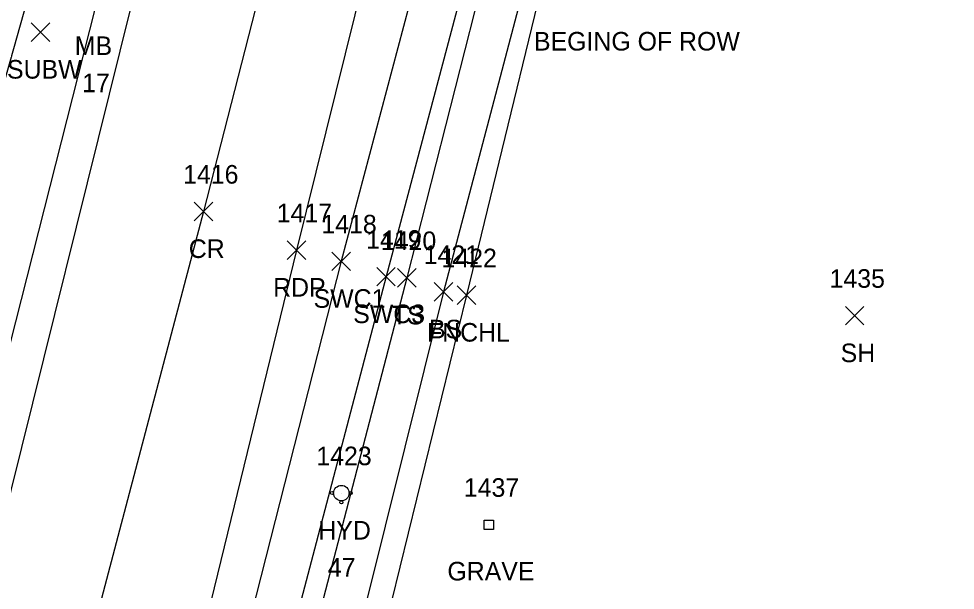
# Model space of a CAD drawing. Extents: x 1477930 to 1480780, y 774090 to 784647.
# Drawn here: x 1479293.7 to 1479394.4, y 774209.8 to 774271.3 of the extents above; entities that cross this region are included whole.
import ezdxf

# ---------------------------------------------------------------- set-up
doc = ezdxf.new("R2010")
doc.units = 0
for name, color, linetype in [('L_A', 7, 'Continuous'), ('L_C', 7, 'Continuous'), ('L_I', 7, 'Continuous'), ('L_TIC', 7, 'Continuous'), ('LCEM', 7, 'Continuous'), ('LELB', 7, 'Continuous'), ('LFNC', 7, 'Continuous'), ('P_A', 7, 'Continuous'), ('P_I', 7, 'Continuous'), ('P_TIC', 7, 'Continuous'), ('PET', 7, 'Continuous'), ('PRC', 7, 'Continuous'), ('R_A', 7, 'Continuous'), ('R_I', 7, 'Continuous'), ('R_TIC', 7, 'Continuous'), ('RSW', 7, 'Continuous'), ('U_A', 7, 'Continuous'), ('U_C', 7, 'Continuous'), ('U_I', 7, 'Continuous'), ('U_TIC', 7, 'Continuous'), ('UWFH', 7, 'Continuous')]:
    doc.layers.add(name, color=color, linetype=linetype)

msp = doc.modelspace()

# ---------------------------------------------------------------- linework, layer by layer
at = {"layer": 'L_TIC'}
for points in [[(1479334.38, 774242.42), (1479336.38, 774244.42)], [(1479336.38, 774242.42), (1479334.38, 774244.42)], [(1479338.33, 774240.92), (1479340.33, 774242.92)], [(1479340.33, 774240.92), (1479338.33, 774242.92)], [(1479340.81, 774240.57), (1479342.81, 774242.57)], [(1479342.81, 774240.57), (1479340.81, 774242.57)], [(1479382.55, 774238.36), (1479384.55, 774240.36)], [(1479384.55, 774238.36), (1479382.55, 774240.36)]]:
    msp.add_lwpolyline(points, dxfattribs=at)
at = {"layer": 'LCEM'}
for p, q in [((1479343.71, 774216.37), (1479343.71, 774217.37)), ((1479343.71, 774217.37), (1479344.71, 774217.37)), ((1479344.21, 774216.87), (1479344.21, 774216.87)), ((1479344.21, 774216.87), (1479344.21, 774216.87)), ((1479344.71, 774217.37), (1479344.71, 774216.37)), ((1479344.71, 774216.37), (1479343.71, 774216.37))]:
    msp.add_line(p, q, dxfattribs=at)
at = {"layer": 'LELB'}
for points in [[(1479286.59, 774212.27), (1479303.75, 774279.72), (1479306.97, 774294.46), (1479314.06, 774320.63), (1479317.48, 774329.95), (1479319.72, 774342.37), (1479300.83, 774349.59), (1479294.56, 774350.02), (1479293.95, 774358.81)], [(1479277.2, 774214.02), (1479283.47, 774234), (1479297.19, 774282.52), (1479300.07, 774295.97), (1479304.88, 774316.5), (1479296.39, 774315.47)], [(1479347.88, 774292.52), (1479335.38, 774243.42), (1479325.08, 774203.75), (1479322.82, 774199.36), (1479320.92, 774190.73)], [(1479352.42, 774291.65), (1479339.33, 774241.92), (1479328.89, 774200.01), (1479326.98, 774198.39), (1479326.95, 774190)]]:
    msp.add_lwpolyline(points, dxfattribs=at)
at = {"layer": 'LFNC'}
msp.add_lwpolyline([(1479353.25, 774288.66), (1479341.81, 774241.57), (1479331.04, 774197.67)], dxfattribs=at)
at = {"layer": 'P_TIC'}
for points in [[(1479312.51, 774249.57), (1479314.51, 774251.57)], [(1479314.51, 774249.57), (1479312.51, 774251.57)], [(1479322.53, 774245.41), (1479324.53, 774247.41)], [(1479324.53, 774245.41), (1479322.53, 774247.41)]]:
    msp.add_lwpolyline(points, dxfattribs=at)
at = {"layer": 'PET'}
for points in [[(1479290.45, 774211), (1479306.91, 774277.39), (1479311.78, 774295.77), (1479318.73, 774320.25), (1479320.95, 774328.78), (1479324.18, 774341.9), (1479331.38, 774365.72), (1479345.79, 774423.22), (1479362.09, 774490.12), (1479368.03, 774516.32), (1479374.9, 774550.83), (1479383.52, 774593.51), (1479391.98, 774640.39), (1479380.39, 774660.29), (1479367.57, 774658.29), (1479344.84, 774648.04), (1479309.03, 774631.85), (1479275.88, 774616.72), (1479247.66, 774604.4), (1479226.65, 774595.78), (1479182.4, 774576.78), (1479137.48, 774556.65)], [(1479393.7, 774517.71), (1479389.34, 774499.77), (1479385.65, 774485.2), (1479372.47, 774434.64), (1479369.27, 774419.38), (1479364.55, 774403.36), (1479358.32, 774380), (1479344.31, 774327.21), (1479344.11, 774325.21), (1479340.22, 774308.9), (1479335.03, 774292.91), (1479323.53, 774246.41), (1479312.91, 774202.88), (1479309.56, 774191.22), (1479295.39, 774137.13)]]:
    msp.add_lwpolyline(points, dxfattribs=at)
at = {"layer": 'PRC'}
msp.add_lwpolyline([(1479418.32, 774694.97), (1479413.6, 774667.54), (1479403.41, 774616.88), (1479393.18, 774569.31), (1479382.15, 774520.62), (1479370.95, 774473.44), (1479362, 774437.8), (1479350.26, 774392.93), (1479347.88, 774382.5), (1479334.29, 774330.6), (1479333.84, 774328.63), (1479325.02, 774295.54), (1479313.51, 774250.57), (1479296.99, 774187.82), (1479284.93, 774140.68)], dxfattribs=at)
at = {"layer": 'R_TIC'}
for points in [[(1479327.32, 774244.21), (1479329.32, 774246.21)], [(1479329.32, 774244.21), (1479327.32, 774246.21)], [(1479332.15, 774242.56), (1479334.15, 774244.56)], [(1479334.15, 774242.56), (1479332.15, 774244.56)]]:
    msp.add_lwpolyline(points, dxfattribs=at)
at = {"layer": 'RSW'}
for points in [[(1479445.73, 774683.18), (1479436.47, 774645.61), (1479432.44, 774628.24), (1479428.42, 774611.14), (1479416.86, 774563.55), (1479405.32, 774516.05), (1479399.83, 774493.77), (1479397.14, 774483.55), (1479383.7, 774432.42), (1479378.78, 774414.66), (1479376, 774403.93), (1479368.41, 774376.23), (1479354.39, 774323.87), (1479354.03, 774322.36), (1479349.26, 774304.31), (1479346.2, 774292.81), (1479333.15, 774243.56), (1479321.64, 774199.64), (1479319.46, 774190.5)], [(1479439.59, 774678.84), (1479428.06, 774631.68), (1479427.69, 774629.39), (1479423.62, 774612.61), (1479412.13, 774564.62), (1479400.05, 774515.9), (1479395.35, 774496.7), (1479392.07, 774484.83), (1479378.7, 774433.47), (1479373.97, 774416.64), (1479370.99, 774405.04), (1479364.01, 774378.3), (1479349.72, 774325.26), (1479349.32, 774323.81), (1479344.48, 774305.55), (1479341.14, 774293.48), (1479328.32, 774245.21), (1479314.62, 774191.4)]]:
    msp.add_lwpolyline(points, dxfattribs=at)
at = {"layer": 'U_TIC'}
for points in [[(1479294.98, 774268.87), (1479296.98, 774270.87)], [(1479296.98, 774268.87), (1479294.98, 774270.87)]]:
    msp.add_lwpolyline(points, dxfattribs=at)
at = {"layer": 'UWFH'}
msp.add_line((1479328.35, 774220.27), (1479328.35, 774220.27), dxfattribs=at)
for centre, radius in [((1479328.35, 774220.27), 0.833), ((1479327.35, 774220.27), 0.167), ((1479329.35, 774220.27), 0.167), ((1479328.35, 774219.27), 0.167)]:
    msp.add_circle(centre, radius, dxfattribs=at)

# ---------------------------------------------------------------- texts
at = {"layer": 'L_A'}
for s, p in [('MB', (1479299.68, 774267.41)), ('TS', (1479333.79, 774238.42)), ('BS', (1479337.77, 774236.92)), ('FNCHL', (1479337.56, 774236.57)), ('SH', (1479382.04, 774234.36)), ('GRAVE', (1479339.75, 774210.87))]:
    msp.add_text(s, height=2, dxfattribs=at).set_placement(p)
at = {"layer": 'L_C'}
for s, p in [('BEGING OF ROW', (1479349.06, 774267.89)), ('17', (1479300.47, 774263.41))]:
    msp.add_text(s, height=2, dxfattribs=at).set_placement(p)
at = {"layer": 'L_I'}
for s, p in [('1420', (1479332.6, 774246.42)), ('1421', (1479337.2, 774244.92)), ('1422', (1479339.12, 774244.57)), ('1435', (1479380.85, 774242.36)), ('1437', (1479341.52, 774219.87))]:
    msp.add_text(s, height=2, dxfattribs=at).set_placement(p)
at = {"layer": 'P_A'}
for s, p in [('CR', (1479311.94, 774245.57)), ('RDP', (1479321.01, 774241.41))]:
    msp.add_text(s, height=2, dxfattribs=at).set_placement(p)
at = {"layer": 'P_I'}
for s, p in [('1416', (1479311.33, 774253.57)), ('1417', (1479321.4, 774249.41))]:
    msp.add_text(s, height=2, dxfattribs=at).set_placement(p)
at = {"layer": 'R_A'}
for s, p in [('SWC1', (1479325.36, 774240.21)), ('SWC3', (1479329.62, 774238.56))]:
    msp.add_text(s, height=2, dxfattribs=at).set_placement(p)
at = {"layer": 'R_I'}
for s, p in [('1418', (1479326.2, 774248.21)), ('1419', (1479331.02, 774246.56))]:
    msp.add_text(s, height=2, dxfattribs=at).set_placement(p)
at = {"layer": 'U_A'}
for s, p in [('SUBW', (1479292.39, 774264.87)), ('HYD', (1479325.87, 774215.27))]:
    msp.add_text(s, height=2, dxfattribs=at).set_placement(p)
at = {"layer": 'U_C'}
msp.add_text('47', height=2, dxfattribs=at).set_placement((1479326.89, 774211.27))
at = {"layer": 'U_I'}
msp.add_text('1423', height=2, dxfattribs=at).set_placement((1479325.66, 774223.27))

doc.saveas('drawing.dxf')
